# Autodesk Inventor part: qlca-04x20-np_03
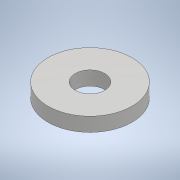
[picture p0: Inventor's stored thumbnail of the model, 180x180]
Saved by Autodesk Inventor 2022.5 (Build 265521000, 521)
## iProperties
Part Number: qlca-04x20-np_03
Material: 一般
Document SubType Name: Modeling
Designer: ImaoCorp
Density: 1 g/cm^3
Appearance: 既定
Author: ImaoCorp
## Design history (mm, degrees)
feature "qlca-04x20-np_03"
node "ソリッド1"
